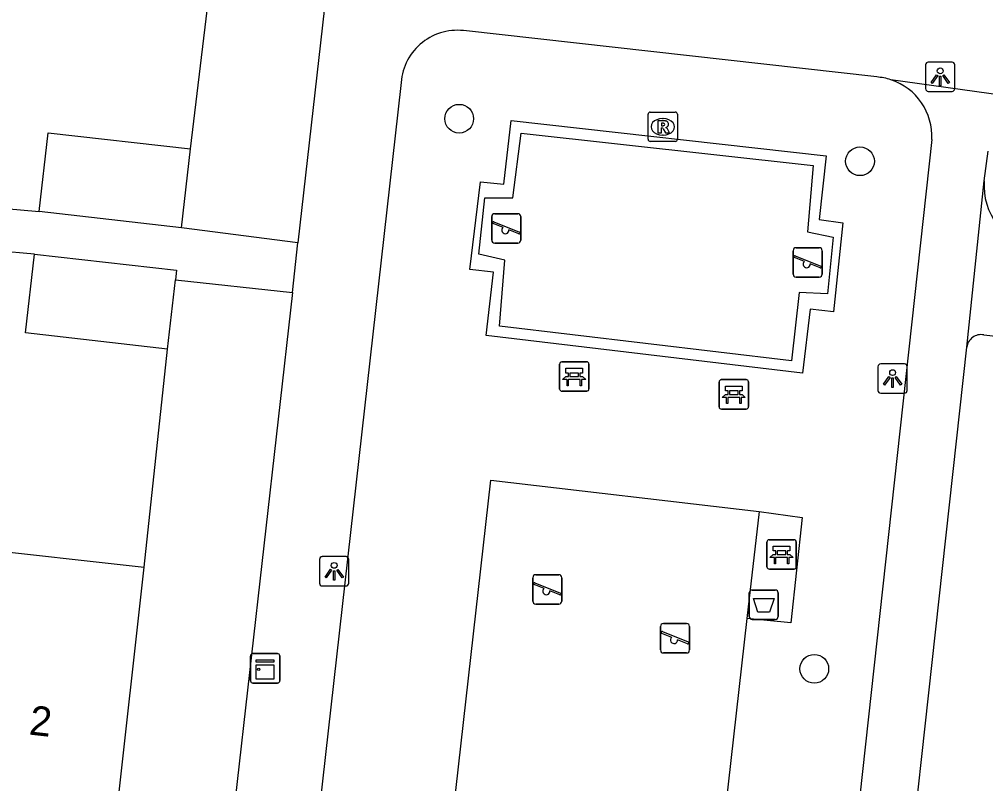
# Model space of a CAD drawing. Extents: x 161928 to 163055, y 386475 to 387428.
# Drawn here: x 162145.03 to 162177.94, y 386825.3 to 386851.33 of the extents above; entities that cross this region are included whole.
import ezdxf

# ---------------------------------------------------------------- set-up
doc = ezdxf.new("R2010")
doc.units = 0
for name, color, linetype in [('IMGEO_Afvalbak', 7, 'Continuous'), ('IMGEO_Bank', 7, 'Continuous'), ('IMGEO_Boom', 7, 'Continuous'), ('IMGEO_Groenvoorziening', 7, 'Continuous'), ('IMGEO_Hek', 7, 'Continuous'), ('IMGEO_Kast', 7, 'Continuous'), ('IMGEO_Lichtpunt', 7, 'Continuous'), ('IMGEO_Pand', 7, 'Continuous'), ('IMGEO_Pand_nummerreeks', 7, 'Continuous'), ('IMGEO_Parkeervlak_open', 7, 'Continuous'), ('IMGEO_Rijbaan_lokaal_open', 7, 'Continuous'), ('IMGEO_Rioolput', 7, 'Continuous'), ('IMGEO_Speelvoorziening', 7, 'Continuous'), ('IMGEO_Voetpad_gesloten', 7, 'Continuous'), ('IMGEO_Voetpad_open', 7, 'Continuous')]:
    doc.layers.add(name, color=color, linetype=linetype)

msp = doc.modelspace()

# ---------------------------------------------------------------- linework, layer by layer
at = {"layer": 'IMGEO_Afvalbak'}
for p, q in [((162169.883, 386830.996), (162169.883, 386831.796)), ((162169.883, 386831.796), (162169.883, 386830.996)), ((162169.983, 386831.896), (162170.773, 386831.896)), ((162170.773, 386831.896), (162169.983, 386831.896)), ((162170.873, 386831.796), (162170.873, 386830.996)), ((162170.873, 386830.996), (162170.873, 386831.796)), ((162170.773, 386830.896), (162169.983, 386830.896)), ((162169.983, 386830.896), (162170.773, 386830.896))]:
    msp.add_line(p, q, dxfattribs=at)
msp.add_lwpolyline([(162170.026, 386831.61), (162170.73, 386831.61), (162170.581, 386831.14), (162170.175, 386831.14), (162170.026, 386831.61)], dxfattribs=at)
for centre, start, end in [((162169.983, 386831.796), 90, 180), ((162169.983, 386831.796), 90, 180), ((162170.773, 386831.796), 0, 90), ((162170.773, 386831.796), 360, 90), ((162169.983, 386830.996), 180, 270), ((162169.983, 386830.996), 180, 270), ((162170.773, 386830.996), 270, 0), ((162170.773, 386830.996), 270, 0)]:
    msp.add_arc(centre, 0.1, start, end, dxfattribs=at)
at = {"layer": 'IMGEO_Bank'}
for p, q in [((162163.427, 386838.741), (162163.427, 386839.582)), ((162163.427, 386839.582), (162163.427, 386838.741)), ((162163.502, 386839.666), (162164.343, 386839.666)), ((162164.343, 386839.666), (162163.502, 386839.666)), ((162164.427, 386839.591), (162164.427, 386838.75)), ((162164.427, 386838.75), (162164.427, 386839.591)), ((162163.736, 386839.172), (162163.736, 386839.278)), ((162163.78, 386839.278), (162163.78, 386839.172)), ((162164.068, 386839.284), (162163.786, 386839.284)), ((162164.074, 386839.172), (162164.074, 386839.278)), ((162164.118, 386839.278), (162164.118, 386839.172)), ((162164.124, 386839.064), (162163.731, 386839.064)), ((162163.786, 386839.166), (162164.068, 386839.166)), ((162168.86, 386838.134), (162168.86, 386838.975)), ((162168.86, 386838.975), (162168.86, 386838.134)), ((162168.935, 386839.059), (162169.776, 386839.059)), ((162169.776, 386839.059), (162168.935, 386839.059)), ((162169.86, 386838.984), (162169.86, 386838.143)), ((162169.86, 386838.143), (162169.86, 386838.984)), ((162164.352, 386838.666), (162163.511, 386838.666)), ((162163.511, 386838.666), (162164.352, 386838.666)), ((162169.169, 386838.565), (162169.169, 386838.671)), ((162169.213, 386838.671), (162169.213, 386838.565)), ((162169.501, 386838.677), (162169.219, 386838.677)), ((162169.507, 386838.565), (162169.507, 386838.671)), ((162169.551, 386838.671), (162169.551, 386838.565)), ((162169.557, 386838.457), (162169.164, 386838.457)), ((162169.219, 386838.559), (162169.501, 386838.559)), ((162169.785, 386838.059), (162168.944, 386838.059)), ((162168.944, 386838.059), (162169.785, 386838.059)), ((162170.488, 386832.683), (162170.488, 386833.524)), ((162170.488, 386833.524), (162170.488, 386832.683)), ((162170.563, 386833.608), (162171.404, 386833.608)), ((162171.404, 386833.608), (162170.563, 386833.608)), ((162171.488, 386833.533), (162171.488, 386832.692)), ((162171.488, 386832.692), (162171.488, 386833.533)), ((162171.185, 386833.006), (162170.792, 386833.006)), ((162170.797, 386833.114), (162170.797, 386833.22)), ((162170.841, 386833.22), (162170.841, 386833.114)), ((162171.129, 386833.226), (162170.847, 386833.226)), ((162170.847, 386833.108), (162171.129, 386833.108)), ((162171.135, 386833.114), (162171.135, 386833.22)), ((162171.179, 386833.22), (162171.179, 386833.114)), ((162171.413, 386832.608), (162170.572, 386832.608)), ((162170.572, 386832.608), (162171.413, 386832.608))]:
    msp.add_line(p, q, dxfattribs=at)
for points in [[(162163.73, 386839.284), (162163.644, 386839.284), (162163.644, 386839.445), (162164.207, 386839.445), (162164.207, 386839.284), (162164.124, 386839.284)], [(162163.674, 386839.064), (162163.532, 386839.064), (162163.644, 386839.166), (162163.73, 386839.166)], [(162163.724, 386839.057), (162163.724, 386838.85), (162163.681, 386838.85), (162163.681, 386839.057)], [(162164.124, 386839.166), (162164.207, 386839.166), (162164.319, 386839.064), (162164.18, 386839.064)], [(162164.174, 386839.057), (162164.174, 386838.85), (162164.13, 386838.85), (162164.13, 386839.057)], [(162169.163, 386838.677), (162169.077, 386838.677), (162169.077, 386838.838), (162169.64, 386838.838), (162169.64, 386838.677), (162169.557, 386838.677)], [(162169.107, 386838.457), (162168.965, 386838.457), (162169.077, 386838.559), (162169.163, 386838.559)], [(162169.157, 386838.45), (162169.157, 386838.243), (162169.114, 386838.243), (162169.114, 386838.45)], [(162169.557, 386838.559), (162169.64, 386838.559), (162169.752, 386838.457), (162169.613, 386838.457)], [(162169.607, 386838.45), (162169.607, 386838.243), (162169.563, 386838.243), (162169.563, 386838.45)], [(162170.791, 386833.226), (162170.705, 386833.226), (162170.705, 386833.387), (162171.268, 386833.387), (162171.268, 386833.226), (162171.185, 386833.226)], [(162170.735, 386833.006), (162170.593, 386833.006), (162170.705, 386833.108), (162170.791, 386833.108)], [(162170.785, 386832.999), (162170.785, 386832.792), (162170.742, 386832.792), (162170.742, 386832.999)], [(162171.185, 386833.108), (162171.268, 386833.108), (162171.38, 386833.006), (162171.241, 386833.006)], [(162171.235, 386832.999), (162171.235, 386832.792), (162171.191, 386832.792), (162171.191, 386832.999)]]:
    msp.add_lwpolyline(points, dxfattribs=at)
for centre, radius, start, end in [((162163.505, 386839.588), 0.0779, 92.4484, 184.2845), ((162163.505, 386839.588), 0.0779, 92.4484, 184.2845), ((162164.349, 386839.588), 0.0779, 2.4484, 94.2845), ((162164.349, 386839.588), 0.0779, 2.4484, 94.2845), ((162163.729, 386839.277), 0.00671, 2.8957, 87.1043), ((162163.786, 386839.277), 0.00671, 92.8957, 177.1043), ((162164.068, 386839.277), 0.00671, 2.8957, 87.1043), ((162164.125, 386839.277), 0.00671, 92.8957, 177.1043), ((162163.674, 386839.057), 0.00671, 2.8957, 87.1043), ((162163.731, 386839.057), 0.00671, 92.8957, 177.1043), ((162163.729, 386839.173), 0.00671, 272.8957, 357.1043), ((162163.786, 386839.173), 0.00671, 182.8957, 267.1043), ((162164.068, 386839.173), 0.00671, 272.8957, 357.1043), ((162164.125, 386839.173), 0.00671, 182.8957, 267.1043), ((162164.123, 386839.057), 0.00671, 2.8957, 87.1043), ((162164.18, 386839.057), 0.00671, 92.8957, 177.1043), ((162168.938, 386838.981), 0.0779, 92.4484, 184.2845), ((162168.938, 386838.981), 0.0779, 92.4484, 184.2845), ((162169.782, 386838.981), 0.0779, 2.4484, 94.2845), ((162169.782, 386838.981), 0.0779, 2.4484, 94.2845), ((162163.505, 386838.744), 0.0779, 182.4484, 274.2845), ((162163.505, 386838.744), 0.0779, 182.4484, 274.2845), ((162164.349, 386838.744), 0.0779, 272.4484, 4.2845), ((162164.349, 386838.744), 0.0779, 272.4484, 4.2845), ((162169.162, 386838.67), 0.00671, 2.8957, 87.1043), ((162169.219, 386838.67), 0.00671, 92.8957, 177.1043), ((162169.501, 386838.67), 0.00671, 2.8957, 87.1043), ((162169.558, 386838.67), 0.00671, 92.8957, 177.1043), ((162169.107, 386838.45), 0.00671, 2.8957, 87.1043), ((162169.164, 386838.45), 0.00671, 92.8957, 177.1043), ((162169.162, 386838.566), 0.00671, 272.8957, 357.1043), ((162169.219, 386838.566), 0.00671, 182.8957, 267.1043), ((162169.501, 386838.566), 0.00671, 272.8957, 357.1043), ((162169.558, 386838.566), 0.00671, 182.8957, 267.1043), ((162169.556, 386838.45), 0.00671, 2.8957, 87.1043), ((162169.613, 386838.45), 0.00671, 92.8957, 177.1043), ((162168.938, 386838.137), 0.0779, 182.4484, 274.2845), ((162168.938, 386838.137), 0.0779, 182.4484, 274.2845), ((162169.782, 386838.137), 0.0779, 272.4484, 4.2845), ((162169.782, 386838.137), 0.0779, 272.4484, 4.2845), ((162170.566, 386833.53), 0.0779, 92.4484, 184.2845), ((162170.566, 386833.53), 0.0779, 92.4484, 184.2845), ((162171.41, 386833.53), 0.0779, 2.4484, 94.2845), ((162171.41, 386833.53), 0.0779, 2.4484, 94.2845), ((162170.735, 386832.999), 0.00671, 2.8957, 87.1043), ((162170.792, 386832.999), 0.00671, 92.8957, 177.1043), ((162170.79, 386833.219), 0.00671, 2.8957, 87.1043), ((162170.79, 386833.115), 0.00671, 272.8957, 357.1043), ((162170.847, 386833.219), 0.00671, 92.8957, 177.1043), ((162170.847, 386833.115), 0.00671, 182.8957, 267.1043), ((162171.129, 386833.219), 0.00671, 2.8957, 87.1043), ((162171.129, 386833.115), 0.00671, 272.8957, 357.1043), ((162171.186, 386833.219), 0.00671, 92.8957, 177.1043), ((162171.186, 386833.115), 0.00671, 182.8957, 267.1043), ((162171.184, 386832.999), 0.00671, 2.8957, 87.1043), ((162171.241, 386832.999), 0.00671, 92.8957, 177.1043), ((162170.566, 386832.686), 0.0779, 182.4484, 274.2845), ((162170.566, 386832.686), 0.0779, 182.4484, 274.2845), ((162171.41, 386832.686), 0.0779, 272.4484, 4.2845), ((162171.41, 386832.686), 0.0779, 272.4484, 4.2845)]:
    msp.add_arc(centre, radius, start, end, dxfattribs=at)
at = {"layer": 'IMGEO_Boom'}
for centre in [(162160.008, 386847.945), (162173.658, 386846.495), (162172.102, 386829.213)]:
    msp.add_circle(centre, 0.489, dxfattribs=at)
at = {"layer": 'IMGEO_Groenvoorziening'}
for points in [[(162150.855, 386846.916), (162151.734, 386854.186)], [(162149.279, 386832.677), (162150.073, 386840.103)], [(162169.807, 386830.931), (162168.366, 386818.134), (162159.221, 386819.136), (162161.084, 386835.638), (162170.224, 386834.572)]]:
    msp.add_lwpolyline(points, dxfattribs=at)
at = {"layer": 'IMGEO_Hek'}
msp.add_lwpolyline([(162171.321, 386839.704), (162161.379, 386840.876), (162161.567, 386843.128), (162160.674, 386843.335), (162160.879, 386845.248), (162161.831, 386845.248), (162162.122, 386847.455), (162172.068, 386846.355), (162171.866, 386844.091), (162172.75, 386843.909), (162172.552, 386841.978), (162171.59, 386842.024), (162171.321, 386839.704)], dxfattribs=at)
at = {"layer": 'IMGEO_Kast'}
for p, q in [((162152.975, 386829.73), (162153.816, 386829.73)), ((162153.816, 386829.73), (162152.975, 386829.73)), ((162152.9, 386828.805), (162152.9, 386829.646)), ((162152.9, 386829.646), (162152.9, 386828.805)), ((162153.9, 386829.655), (162153.9, 386828.814)), ((162153.9, 386828.814), (162153.9, 386829.655)), ((162153.825, 386828.73), (162152.984, 386828.73)), ((162152.984, 386828.73), (162153.825, 386828.73))]:
    msp.add_line(p, q, dxfattribs=at)
for points in [[(162153.095, 386829.52), (162153.695, 386829.52), (162153.695, 386829.435), (162153.095, 386829.435), (162153.095, 386829.52)], [(162153.095, 386829.345), (162153.695, 386829.345), (162153.695, 386828.856), (162153.095, 386828.856), (162153.095, 386829.345)]]:
    msp.add_lwpolyline(points, dxfattribs=at)
msp.add_circle((162153.179, 386829.194), 0.0377, dxfattribs=at)
for centre, start, end in [((162152.978, 386829.652), 92.4484, 184.2845), ((162152.978, 386829.652), 92.4484, 184.2845), ((162153.822, 386829.652), 2.4484, 94.2845), ((162153.822, 386829.652), 2.4484, 94.2845), ((162152.978, 386828.808), 182.4484, 274.2845), ((162152.978, 386828.808), 182.4484, 274.2845), ((162153.822, 386828.808), 272.4484, 4.2845), ((162153.822, 386828.808), 272.4484, 4.2845)]:
    msp.add_arc(centre, 0.0779, start, end, dxfattribs=at)
at = {"layer": 'IMGEO_Lichtpunt'}
for p, q in [((162175.891, 386849.775), (162175.891, 386848.968)), ((162175.891, 386849.775), (162175.891, 386848.968)), ((162176.793, 386849.87), (162175.985, 386849.87)), ((162176.793, 386849.87), (162175.985, 386849.87)), ((162176.887, 386848.968), (162176.887, 386849.775)), ((162176.887, 386848.968), (162176.887, 386849.775)), ((162175.985, 386848.874), (162176.793, 386848.874)), ((162175.985, 386848.874), (162176.793, 386848.874)), ((162175.172, 386839.596), (162174.364, 386839.596)), ((162175.172, 386839.596), (162174.364, 386839.596)), ((162174.27, 386839.501), (162174.27, 386838.694)), ((162174.27, 386839.501), (162174.27, 386838.694)), ((162175.266, 386838.694), (162175.266, 386839.501)), ((162175.266, 386838.694), (162175.266, 386839.501)), ((162174.364, 386838.6), (162175.172, 386838.6)), ((162174.364, 386838.6), (162175.172, 386838.6)), ((162156.153, 386833.032), (162155.345, 386833.032)), ((162156.153, 386833.032), (162155.345, 386833.032)), ((162155.251, 386832.937), (162155.251, 386832.13)), ((162155.251, 386832.937), (162155.251, 386832.13)), ((162156.247, 386832.13), (162156.247, 386832.937)), ((162156.247, 386832.13), (162156.247, 386832.937)), ((162155.345, 386832.036), (162156.153, 386832.036)), ((162155.345, 386832.036), (162156.153, 386832.036))]:
    msp.add_line(p, q, dxfattribs=at)
for points in [[(162176.265, 386849.439), (162176.304, 386849.411), (162176.116, 386849.149), (162176.078, 386849.176), (162176.265, 386849.439)], [(162176.367, 386849.391), (162176.414, 386849.391), (162176.414, 386849.069), (162176.367, 386849.069), (162176.367, 386849.391)], [(162176.477, 386849.411), (162176.515, 386849.438), (162176.702, 386849.176), (162176.663, 386849.148), (162176.477, 386849.411)], [(162174.644, 386839.165), (162174.683, 386839.137), (162174.495, 386838.875), (162174.457, 386838.902), (162174.644, 386839.165)], [(162174.746, 386839.117), (162174.793, 386839.117), (162174.793, 386838.795), (162174.746, 386838.795), (162174.746, 386839.117)], [(162174.856, 386839.137), (162174.894, 386839.164), (162175.081, 386838.902), (162175.042, 386838.874), (162174.856, 386839.137)], [(162155.625, 386832.601), (162155.664, 386832.573), (162155.476, 386832.311), (162155.438, 386832.338), (162155.625, 386832.601)], [(162155.727, 386832.553), (162155.774, 386832.553), (162155.774, 386832.231), (162155.727, 386832.231), (162155.727, 386832.553)], [(162155.837, 386832.573), (162155.875, 386832.6), (162156.062, 386832.338), (162156.023, 386832.31), (162155.837, 386832.573)]]:
    msp.add_lwpolyline(points, dxfattribs=at)
for centre in [(162176.39, 386849.573), (162174.769, 386839.299), (162155.75, 386832.735)]:
    msp.add_circle(centre, 0.0994, dxfattribs=at)
for centre, start, end in [((162175.985, 386849.775), 90, 180), ((162175.985, 386849.775), 90, 180), ((162176.793, 386849.775), 0, 90), ((162176.793, 386849.775), 0, 90), ((162175.985, 386848.968), 180, 270), ((162175.985, 386848.968), 180, 270), ((162176.793, 386848.968), 270, 0), ((162176.793, 386848.968), 270, 360), ((162174.364, 386839.501), 90, 180), ((162174.364, 386839.501), 90, 180), ((162175.172, 386839.501), 0, 90), ((162175.172, 386839.501), 0, 90), ((162174.364, 386838.694), 180, 270), ((162174.364, 386838.694), 180, 270), ((162175.172, 386838.694), 270, 0), ((162175.172, 386838.694), 270, 360), ((162155.345, 386832.937), 90, 180), ((162155.345, 386832.937), 90, 180), ((162156.153, 386832.937), 0, 90), ((162156.153, 386832.937), 0, 90), ((162155.345, 386832.13), 180, 270), ((162155.345, 386832.13), 180, 270), ((162156.153, 386832.13), 270, 0), ((162156.153, 386832.13), 270, 360)]:
    msp.add_arc(centre, 0.0946, start, end, dxfattribs=at)
at = {"layer": 'IMGEO_Pand'}
for points in [[(162145.704, 386844.784), (162146.01, 386847.468), (162150.855, 386846.916)], [(162150.55, 386844.232), (162150.855, 386846.916)], [(162150.55, 386844.232), (162145.704, 386844.784)], [(162150.073, 386840.103), (162145.238, 386840.653), (162145.544, 386843.337)], [(162145.544, 386843.337), (162150.379, 386842.786), (162150.342, 386842.461)], [(162150.073, 386840.103), (162150.342, 386842.461)], [(162143.35, 386833.337), (162149.279, 386832.677)], [(162148.325, 386824.109), (162149.279, 386832.677)]]:
    msp.add_lwpolyline(points, dxfattribs=at)
at = {"layer": 'IMGEO_Parkeervlak_open'}
msp.add_lwpolyline([(162177.876, 386840.584), (162181.361, 386840.187)], dxfattribs=at)
msp.add_arc((162177.78, 386840.106), 0.487, 78.6357, 173.5716, dxfattribs=at)
at = {"layer": 'IMGEO_Rijbaan_lokaal_open'}
msp.add_lwpolyline([(162177.889, 386845.834), (162178.02, 386846.839)], dxfattribs=at)
msp.add_arc((162180.048, 386845.663), 2.166, 175.4631, 259.5488, dxfattribs=at)
at = {"layer": 'IMGEO_Rioolput'}
for p, q in [((162166.516, 386848.169), (162167.368, 386848.169)), ((162166.441, 386847.243), (162166.441, 386848.095)), ((162166.929, 386847.949), (162166.954, 386847.949)), ((162167.442, 386848.095), (162167.442, 386847.243)), ((162167.368, 386847.169), (162166.516, 386847.169)), ((162166.952, 386847.389), (162166.927, 386847.389))]:
    msp.add_line(p, q, dxfattribs=at)
for points in [[(162166.516, 386848.169), (162167.368, 386848.169)], [(162166.441, 386847.243), (162166.441, 386848.095)], [(162167.03, 386847.867), (162166.778, 386847.869), (162166.778, 386847.469)], [(162167.442, 386848.095), (162167.442, 386847.243)], [(162166.778, 386847.469), (162166.902, 386847.469), (162166.902, 386847.631), (162166.913, 386847.631)], [(162166.956, 386847.788), (162166.902, 386847.788), (162166.902, 386847.707)], [(162166.902, 386847.707), (162166.954, 386847.707)], [(162166.96, 386847.602), (162167.031, 386847.469), (162167.171, 386847.469), (162167.106, 386847.595)], [(162167.368, 386847.169), (162166.516, 386847.169)]]:
    msp.add_lwpolyline(points, dxfattribs=at)
for centre, radius, start, end in [((162166.518, 386848.093), 0.0765, 91.552, 178.448), ((162166.518, 386848.093), 0.0765, 91.552, 178.448), ((162167.366, 386848.093), 0.0765, 1.552, 88.448), ((162167.366, 386848.093), 0.0765, 1.552, 88.448), ((162167.029, 386847.757), 0.109, 350.3612, 89.416), ((162166.912, 386847.578), 0.0533, 26.0293, 88.6989), ((162166.938, 386847.896), 0.19, 274.7715, 282.9687), ((162166.962, 386847.692), 0.0964, 77.0061, 93.1865), ((162166.976, 386847.749), 0.0378, 276.6634, 79.6772), ((162167.027, 386847.757), 0.112, 277.5842, 350.9817), ((162167.011, 386847.542), 0.108, 29.5134, 73.7905), ((162166.518, 386847.245), 0.0765, 181.552, 268.448), ((162166.518, 386847.245), 0.0765, 181.552, 268.448), ((162167.366, 386847.245), 0.0765, 271.552, 358.448), ((162167.366, 386847.245), 0.0765, 271.552, 358.448)]:
    msp.add_arc(centre, radius, start, end, dxfattribs=at)
for centre, major_axis, ratio, start_param, end_param in [((162166.928, 386847.669), (-0.387, 0.002), 0.722429, 4.712389, 7.853982), ((162166.953, 386847.669), (-0.39, 0.002), 0.717154, 1.570796, 4.712389)]:
    msp.add_ellipse(centre, major_axis=major_axis, ratio=ratio, start_param=start_param, end_param=end_param, dxfattribs=at)
at = {"layer": 'IMGEO_Speelvoorziening'}
for p, q in [((162161.117, 386843.81), (162161.117, 386844.61)), ((162161.117, 386844.61), (162161.117, 386843.81)), ((162161.217, 386844.71), (162162.007, 386844.71)), ((162162.007, 386844.71), (162161.217, 386844.71)), ((162162.107, 386844.61), (162162.107, 386843.81)), ((162162.107, 386843.81), (162162.107, 386844.61)), ((162161.5, 386844.238), (162161.161, 386844.375)), ((162161.186, 386844.435), (162162.062, 386844.082)), ((162162.038, 386844.022), (162161.698, 386844.159)), ((162162.007, 386843.71), (162161.217, 386843.71)), ((162161.217, 386843.71), (162162.007, 386843.71)), ((162171.481, 386843.551), (162172.271, 386843.551)), ((162172.271, 386843.551), (162171.481, 386843.551)), ((162171.381, 386842.651), (162171.381, 386843.451)), ((162171.381, 386843.451), (162171.381, 386842.651)), ((162171.764, 386843.079), (162171.425, 386843.216)), ((162171.45, 386843.276), (162172.326, 386842.923)), ((162172.371, 386843.451), (162172.371, 386842.651)), ((162172.371, 386842.651), (162172.371, 386843.451)), ((162172.302, 386842.863), (162171.962, 386843)), ((162172.271, 386842.551), (162171.481, 386842.551)), ((162171.481, 386842.551), (162172.271, 386842.551)), ((162162.614, 386832.416), (162163.404, 386832.416)), ((162163.404, 386832.416), (162162.614, 386832.416)), ((162162.514, 386831.516), (162162.514, 386832.316)), ((162162.514, 386832.316), (162162.514, 386831.516)), ((162162.897, 386831.944), (162162.558, 386832.081)), ((162162.583, 386832.141), (162163.459, 386831.788)), ((162163.504, 386832.316), (162163.504, 386831.516)), ((162163.504, 386831.516), (162163.504, 386832.316)), ((162163.435, 386831.728), (162163.095, 386831.865)), ((162163.404, 386831.416), (162162.614, 386831.416)), ((162162.614, 386831.416), (162163.404, 386831.416)), ((162166.963, 386830.755), (162167.753, 386830.755)), ((162167.753, 386830.755), (162166.963, 386830.755)), ((162166.863, 386829.855), (162166.863, 386830.655)), ((162166.863, 386830.655), (162166.863, 386829.855)), ((162167.246, 386830.283), (162166.907, 386830.42)), ((162166.932, 386830.48), (162167.808, 386830.127)), ((162167.853, 386830.655), (162167.853, 386829.855)), ((162167.853, 386829.855), (162167.853, 386830.655)), ((162167.784, 386830.067), (162167.444, 386830.204)), ((162167.753, 386829.755), (162166.963, 386829.755)), ((162166.963, 386829.755), (162167.753, 386829.755))]:
    msp.add_line(p, q, dxfattribs=at)
for centre, radius, start, end in [((162161.217, 386844.61), 0.1, 90, 180), ((162161.217, 386844.61), 0.1, 90, 180), ((162162.007, 386844.61), 0.1, 0, 90), ((162162.007, 386844.61), 0.1, 360, 90), ((162161.174, 386844.405), 0.0327, 68.078, 248.078), ((162161.579, 386844.148), 0.12, 130.9928, 5.1632), ((162162.05, 386844.052), 0.0327, 248.078, 68.078), ((162161.217, 386843.81), 0.1, 180, 270), ((162161.217, 386843.81), 0.1, 180, 270), ((162162.007, 386843.81), 0.1, 270, 0), ((162162.007, 386843.81), 0.1, 270, 0), ((162171.481, 386843.451), 0.1, 90, 180), ((162171.481, 386843.451), 0.1, 90, 180), ((162172.271, 386843.451), 0.1, 0, 90), ((162172.271, 386843.451), 0.1, 360, 90), ((162171.438, 386843.246), 0.0327, 68.078, 248.078), ((162171.843, 386842.989), 0.12, 130.9928, 5.1632), ((162172.314, 386842.893), 0.0327, 248.078, 68.078), ((162171.481, 386842.651), 0.1, 180, 270), ((162171.481, 386842.651), 0.1, 180, 270), ((162172.271, 386842.651), 0.1, 270, 0), ((162172.271, 386842.651), 0.1, 270, 0), ((162162.614, 386832.316), 0.1, 90, 180), ((162162.614, 386832.316), 0.1, 90, 180), ((162163.404, 386832.316), 0.1, 0, 90), ((162163.404, 386832.316), 0.1, 360, 90), ((162162.571, 386832.111), 0.0327, 68.078, 248.078), ((162162.976, 386831.854), 0.12, 130.9928, 5.1632), ((162163.447, 386831.758), 0.0327, 248.078, 68.078), ((162162.614, 386831.516), 0.1, 180, 270), ((162162.614, 386831.516), 0.1, 180, 270), ((162163.404, 386831.516), 0.1, 270, 0), ((162163.404, 386831.516), 0.1, 270, 0), ((162166.963, 386830.655), 0.1, 90, 180), ((162166.963, 386830.655), 0.1, 90, 180), ((162167.753, 386830.655), 0.1, 0, 90), ((162167.753, 386830.655), 0.1, 360, 90), ((162166.92, 386830.45), 0.0327, 68.078, 248.078), ((162167.325, 386830.193), 0.12, 130.9928, 5.1632), ((162167.796, 386830.097), 0.0327, 248.078, 68.078), ((162166.963, 386829.855), 0.1, 180, 270), ((162166.963, 386829.855), 0.1, 180, 270), ((162167.753, 386829.855), 0.1, 270, 0), ((162167.753, 386829.855), 0.1, 270, 0)]:
    msp.add_arc(centre, radius, start, end, dxfattribs=at)
at = {"layer": 'IMGEO_Voetpad_gesloten'}
for points in [[(162160.931, 386840.564), (162161.182, 386842.717), (162160.369, 386842.812), (162160.733, 386845.794), (162161.524, 386845.716), (162161.781, 386847.879), (162172.502, 386846.676), (162172.273, 386844.511), (162173.079, 386844.397), (162172.752, 386841.369), (162171.956, 386841.462), (162171.696, 386839.284), (162160.931, 386840.564)], [(162171.321, 386839.704), (162161.379, 386840.876), (162161.567, 386843.128), (162160.674, 386843.335), (162160.879, 386845.248), (162161.831, 386845.248), (162162.122, 386847.455), (162172.068, 386846.355), (162171.866, 386844.091), (162172.75, 386843.909), (162172.552, 386841.978), (162171.59, 386842.024), (162171.321, 386839.704)]]:
    msp.add_lwpolyline(points, dxfattribs=at)
at = {"layer": 'IMGEO_Voetpad_open'}
for points in [[(162155.743, 386854.547), (162154.518, 386843.716)], [(162174.227, 386849.366), (162160.151, 386850.945)], [(162180.002, 386848.53), (162174.713, 386849.27)], [(162158.023, 386849.081), (162154.395, 386816.919), (162154.192, 386815.117)], [(162176.1, 386847.236), (162172.565, 386814.959), (162172.371, 386813.189)], [(162177.296, 386840.161), (162177.889, 386845.834)], [(162144.56, 386844.893), (162145.704, 386844.784)], [(162154.518, 386843.716), (162150.55, 386844.232)], [(162154.327, 386842.032), (162154.518, 386843.716)], [(162145.544, 386843.337), (162144.255, 386843.446)], [(162150.342, 386842.461), (162154.327, 386842.032)], [(162154.327, 386842.032), (162151.401, 386816.151), (162151.385, 386816.036), (162151.341, 386815.823)], [(162174.11, 386811.153), (162177.296, 386840.161)], [(162170.224, 386834.572), (162171.69, 386834.361), (162171.302, 386830.783), (162169.807, 386830.931)], [(162170.224, 386834.572), (162169.807, 386830.931)]]:
    msp.add_lwpolyline(points, dxfattribs=at)
for centre, radius, start, end in [((162159.95, 386849.028), 1.928, 84.0168, 178.416), ((162174.083, 386847.358), 2.013, 71.7583, 85.8941), ((162174.084, 386847.351), 2.019, 356.7341, 71.8467)]:
    msp.add_arc(centre, radius, start, end, dxfattribs=at)

# ---------------------------------------------------------------- texts
at = {"layer": 'IMGEO_Pand_nummerreeks'}
msp.add_text('2', height=1, rotation=353.6423, dxfattribs=at).set_placement((162145.333, 386826.978))

doc.saveas('drawing.dxf')
